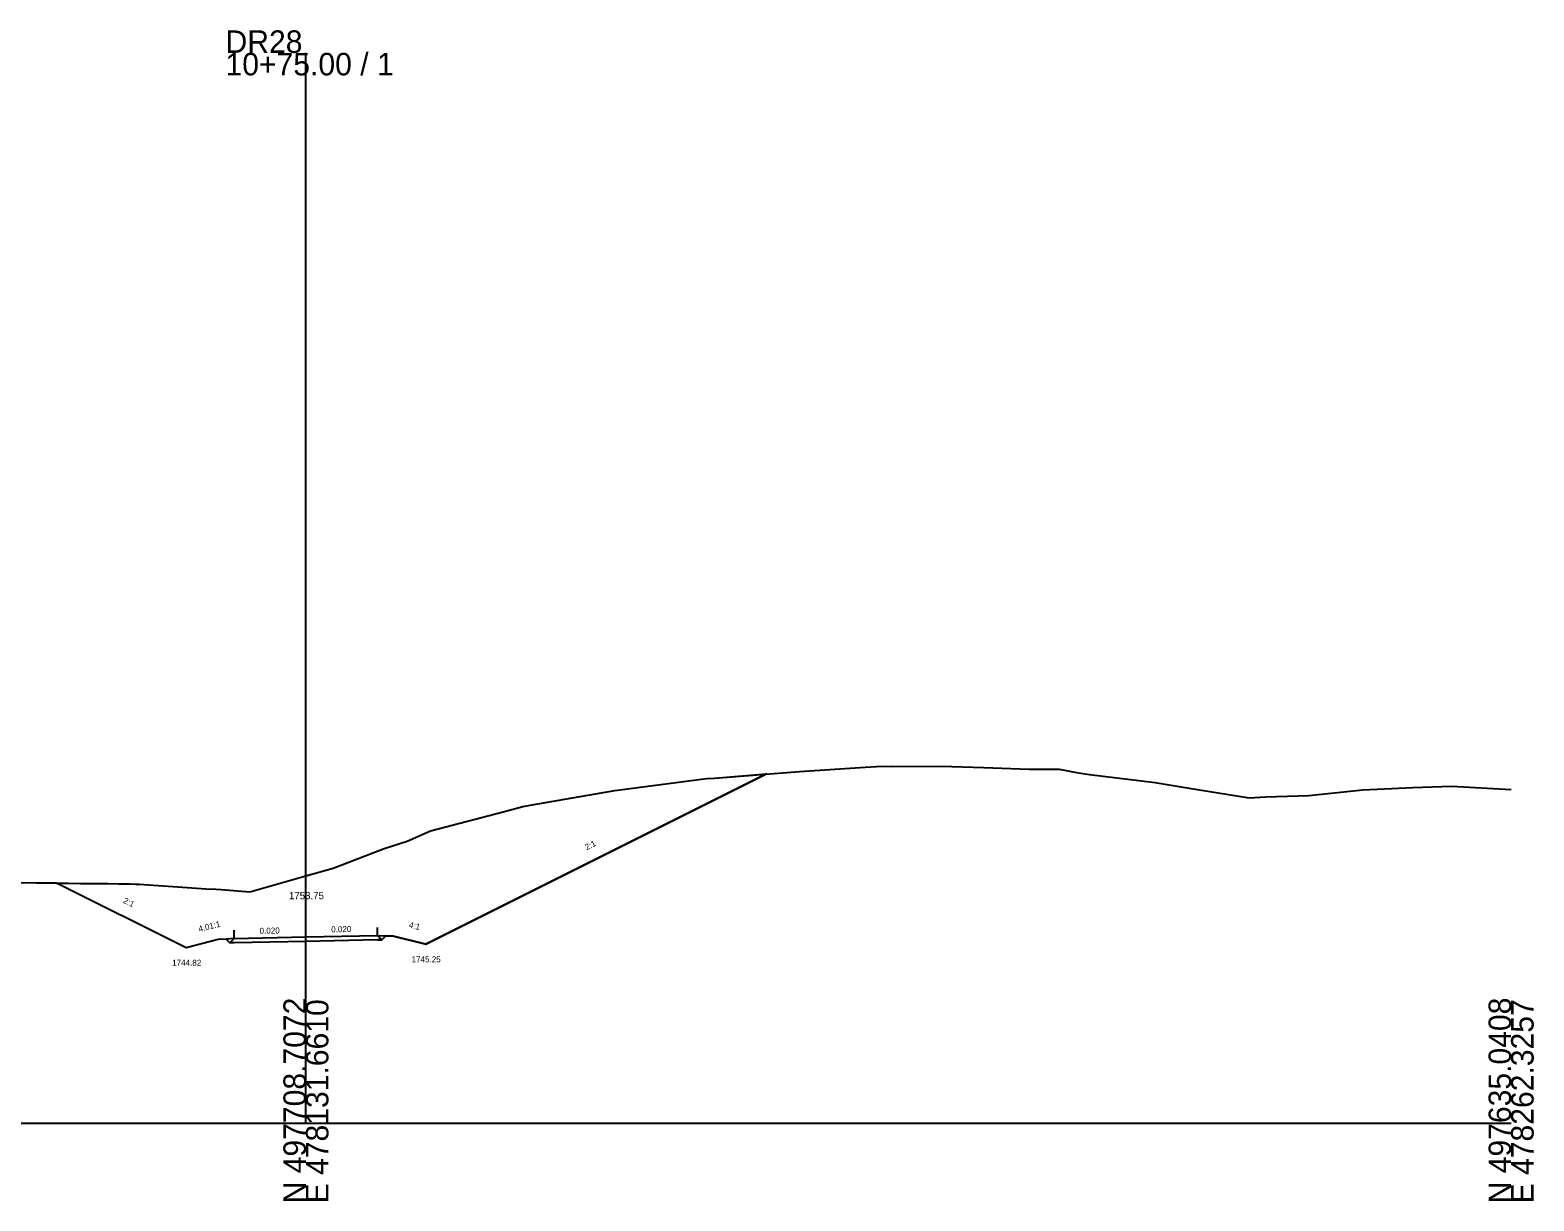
# Model space of a CAD drawing. Extents: x -26 to 303, y -10 to 3689.
# Drawn here: x 115.7 to 302.8, y 1490.3 to 1636 of the extents above; entities that cross this region are included whole.
import ezdxf

# ---------------------------------------------------------------- set-up
doc = ezdxf.new("R2010")
doc.units = 0
for name, color, linetype in [('Exist Cross Section Cell', 7, 'Continuous'), ('Exist XS Center Line Elevation Label', 7, 'Continuous'), ('Exist XS Ground Line', 7, 'Continuous'), ('Prop XS Ditch Slope Text', 7, 'Continuous'), ('Prop XS Ditch Standard Text', 7, 'Continuous'), ('Prop XS Dump Level', 7, 'Continuous'), ('Prop XS Earthwork Shape', 7, 'Continuous'), ('Prop XS EOT Tick Mark', 7, 'Continuous'), ('Prop XS Finish Grade', 7, 'Continuous'), ('Prop XS Finish Grade Earthwork', 7, 'Continuous'), ('Prop XS Finish Grade Pavement', 7, 'Continuous'), ('Prop XS Hydro Typical Ditch Data', 7, 'Continuous'), ('Prop XS Pvmt Edge Slope', 7, 'Continuous'), ('Prop XS SE Text', 7, 'Continuous'), ('Prop XS Shoulder Borrow Shape', 7, 'Continuous'), ('Prop XS Side Slope Text', 7, 'Continuous'), ('Prop XS Subgrade Earthwork', 7, 'Continuous')]:
    doc.layers.add(name, color=color, linetype=linetype)

msp = doc.modelspace()

# ---------------------------------------------------------------- linework, layer by layer
at = {"layer": 'Exist Cross Section Cell'}
for p, q in [((150, 1500), (150, 1633.17)), ((0, 1500), (150, 1500)), ((150, 1500), (300, 1500))]:
    msp.add_line(p, q, dxfattribs=at)
at = {"layer": 'Exist XS Ground Line'}
msp.add_lwpolyline([(113.49, 1529.94), (116.49, 1529.9), (118.04, 1529.88), (118.9, 1529.87), (121.95, 1529.82), (124.63, 1529.8), (125.35, 1529.79), (126.67, 1529.77), (127.52, 1529.76), (128.11, 1529.75), (128.82, 1529.74), (129.24, 1529.73), (134.65, 1529.36), (137.55, 1529.15), (138.78, 1529.09), (139.47, 1529.07), (143.02, 1528.76), (150, 1530.75), (153.38, 1531.71), (159.73, 1534.18), (162.61, 1535.06), (165.5, 1536.38), (174.54, 1538.72), (176.98, 1539.37), (178.87, 1539.74), (188.46, 1541.38), (199.24, 1542.8), (199.94, 1542.86), (200.86, 1542.93), (211.43, 1543.76), (219.6, 1544.29), (221.72, 1544.39), (222.91, 1544.38), (229.06, 1544.39), (234.39, 1544.25), (239.97, 1544.05), (243.74, 1544.05), (245.9, 1543.63), (247.53, 1543.36), (255.7, 1542.39), (259.95, 1541.68), (267.41, 1540.48), (269.46, 1540.59), (274.83, 1540.75), (281.55, 1541.48), (287.78, 1541.76), (292.6, 1541.93), (300, 1541.52)], dxfattribs=at)
at = {"layer": 'Prop XS Dump Level'}
for p, q in [((141.09, 1522.98), (150, 1523.15)), ((150, 1523.15), (158.91, 1523.33))]:
    msp.add_line(p, q, dxfattribs=at)
at = {"layer": 'Prop XS Earthwork Shape'}
for points in [[(135.08, 1521.82), (118.96, 1529.86), (121.95, 1529.82), (124.63, 1529.8), (125.35, 1529.79), (126.67, 1529.77), (127.52, 1529.76), (128.11, 1529.75), (128.82, 1529.74), (129.24, 1529.73), (134.65, 1529.36), (137.55, 1529.15), (138.78, 1529.09), (139.47, 1529.07), (143.02, 1528.76), (150, 1530.75), (153.38, 1531.71), (159.73, 1534.18), (162.61, 1535.06), (165.5, 1536.38), (174.54, 1538.72), (176.98, 1539.37), (178.87, 1539.74), (188.46, 1541.38), (199.24, 1542.8), (199.94, 1542.86), (200.86, 1542.93), (207.31, 1543.44), (164.91, 1522.25), (160.91, 1523.25), (159.93, 1523.29), (159.44, 1522.8), (158.91, 1522.79), (150, 1522.61), (141.09, 1522.43), (140.54, 1522.42), (140.06, 1522.89), (139.09, 1522.82)], [(150, 1522.61), (141.09, 1522.43), (140.54, 1522.42), (140.06, 1522.89), (139.09, 1522.82), (135.08, 1521.82), (118.96, 1529.86), (121.95, 1529.82), (124.63, 1529.8), (125.35, 1529.79), (126.67, 1529.77), (127.52, 1529.76), (128.11, 1529.75), (128.82, 1529.74), (129.24, 1529.73), (134.65, 1529.36), (137.55, 1529.15), (138.78, 1529.09), (139.47, 1529.07), (143.02, 1528.76), (150, 1530.75), (153.38, 1531.71), (159.73, 1534.18), (162.61, 1535.06), (165.5, 1536.38), (174.54, 1538.72), (176.98, 1539.37), (178.87, 1539.74), (188.46, 1541.38), (199.24, 1542.8), (199.94, 1542.86), (200.86, 1542.93), (207.31, 1543.44), (164.91, 1522.25), (160.91, 1523.25), (159.93, 1523.29), (159.44, 1522.8), (158.91, 1522.79)]]:
    msp.add_lwpolyline(points, close=True, dxfattribs=at)
at = {"layer": 'Prop XS EOT Tick Mark'}
for p, q in [((141.09, 1522.98), (141.09, 1523.98)), ((158.91, 1523.33), (158.91, 1524.33))]:
    msp.add_line(p, q, dxfattribs=at)
at = {"layer": 'Prop XS Finish Grade'}
for p, q in [((141.09, 1522.98), (140.06, 1522.89)), ((158.91, 1523.33), (159.93, 1523.29))]:
    msp.add_line(p, q, dxfattribs=at)
at = {"layer": 'Prop XS Finish Grade Earthwork'}
for p, q in [((164.91, 1522.25), (207.31, 1543.44)), ((135.08, 1521.82), (118.96, 1529.86)), ((139.09, 1522.82), (135.08, 1521.82)), ((140.06, 1522.89), (139.09, 1522.82)), ((159.93, 1523.29), (160.91, 1523.25)), ((160.91, 1523.25), (164.91, 1522.25))]:
    msp.add_line(p, q, dxfattribs=at)
at = {"layer": 'Prop XS Finish Grade Pavement'}
for p, q in [((141.09, 1522.98), (150, 1523.15)), ((150, 1523.15), (158.91, 1523.33))]:
    msp.add_line(p, q, dxfattribs=at)
at = {"layer": 'Prop XS Hydro Typical Ditch Data'}
for p, q in [((135.08, 1521.82), (118.96, 1529.86)), ((139.09, 1522.82), (135.08, 1521.82))]:
    msp.add_line(p, q, dxfattribs=at)
at = {"layer": 'Prop XS Pvmt Edge Slope'}
for p, q in [((141.09, 1522.98), (140.54, 1522.42)), ((158.91, 1523.33), (159.44, 1522.8))]:
    msp.add_line(p, q, dxfattribs=at)
at = {"layer": 'Prop XS Shoulder Borrow Shape'}
for points in [[(141.09, 1522.98), (140.06, 1522.89), (140.54, 1522.42)], [(158.91, 1523.33), (159.93, 1523.29), (159.44, 1522.8)]]:
    msp.add_lwpolyline(points, close=True, dxfattribs=at)
at = {"layer": 'Prop XS Subgrade Earthwork'}
for p, q in [((140.54, 1522.42), (140.06, 1522.89)), ((141.09, 1522.43), (140.54, 1522.42)), ((150, 1522.61), (141.09, 1522.43)), ((158.91, 1522.79), (150, 1522.61)), ((158.91, 1522.79), (159.44, 1522.8)), ((159.44, 1522.8), (159.93, 1523.29))]:
    msp.add_line(p, q, dxfattribs=at)

# ---------------------------------------------------------------- texts
at = {"layer": 'Exist Cross Section Cell'}
for s, p in [('DR28', (140, 1633.17)), ('10+75.00 / 1', (140, 1630.37))]:
    msp.add_text(s, height=2.8, dxfattribs=at).set_placement(p)
for s, p in [('N 497708.7072', (150, 1490)), ('E 478131.6610', (152.8, 1490)), ('N 497635.0408', (300, 1490)), ('E 478262.3257', (302.8, 1490))]:
    msp.add_text(s, height=2.8, rotation=90, dxfattribs=at).set_placement(p)
at = {"layer": 'Exist XS Center Line Elevation Label'}
msp.add_text('1753.75', height=0.9, dxfattribs=at).set_placement((147.89, 1527.85))
at = {"layer": 'Prop XS Ditch Slope Text'}
for s, rotation, p in [('4.01:1', 14.0153, (136.72, 1523.77)), ('4:1', 345.9706, (162.76, 1524.34))]:
    msp.add_text(s, height=0.75, rotation=rotation, dxfattribs=at).set_placement(p)
at = {"layer": 'Prop XS Ditch Standard Text'}
for s, p in [('1744.82', (133.35, 1519.57)), ('1745.25', (163.15, 1520))]:
    msp.add_text(s, height=0.75, dxfattribs=at).set_placement(p)
at = {"layer": 'Prop XS Dump Level'}
for p in [(139.09, 1522.78), (160.91, 1523.21)]:
    msp.add_text('Case1', height=0.04, dxfattribs=at).set_placement(p)
at = {"layer": 'Prop XS SE Text'}
for p in [(144.24, 1523.54), (153.15, 1523.72)]:
    msp.add_text('0.020', height=0.75, rotation=1.1458, dxfattribs=at).set_placement(p)
at = {"layer": 'Prop XS Side Slope Text'}
for rotation, p in [(26.5534, (184.94, 1533.93)), (333.4705, (127.18, 1527.44))]:
    msp.add_text('2:1', height=0.75, rotation=rotation, dxfattribs=at).set_placement(p)

doc.saveas('drawing.dxf')
